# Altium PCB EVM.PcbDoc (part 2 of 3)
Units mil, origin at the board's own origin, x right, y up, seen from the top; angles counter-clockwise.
Board outline 4950 x 3450 mil, 6 copper layers (Top Layer, Power Layer 1 (PWR), Power Layer 2 (GND), Power Layer 3 (PWR), Power Layer 4 (GND), Bottom Layer), stack 58.4 mil thick; 378 components, 191 nets, 2749 pads, 0 vias.
Unrouted connection lines stored in the file: 482.
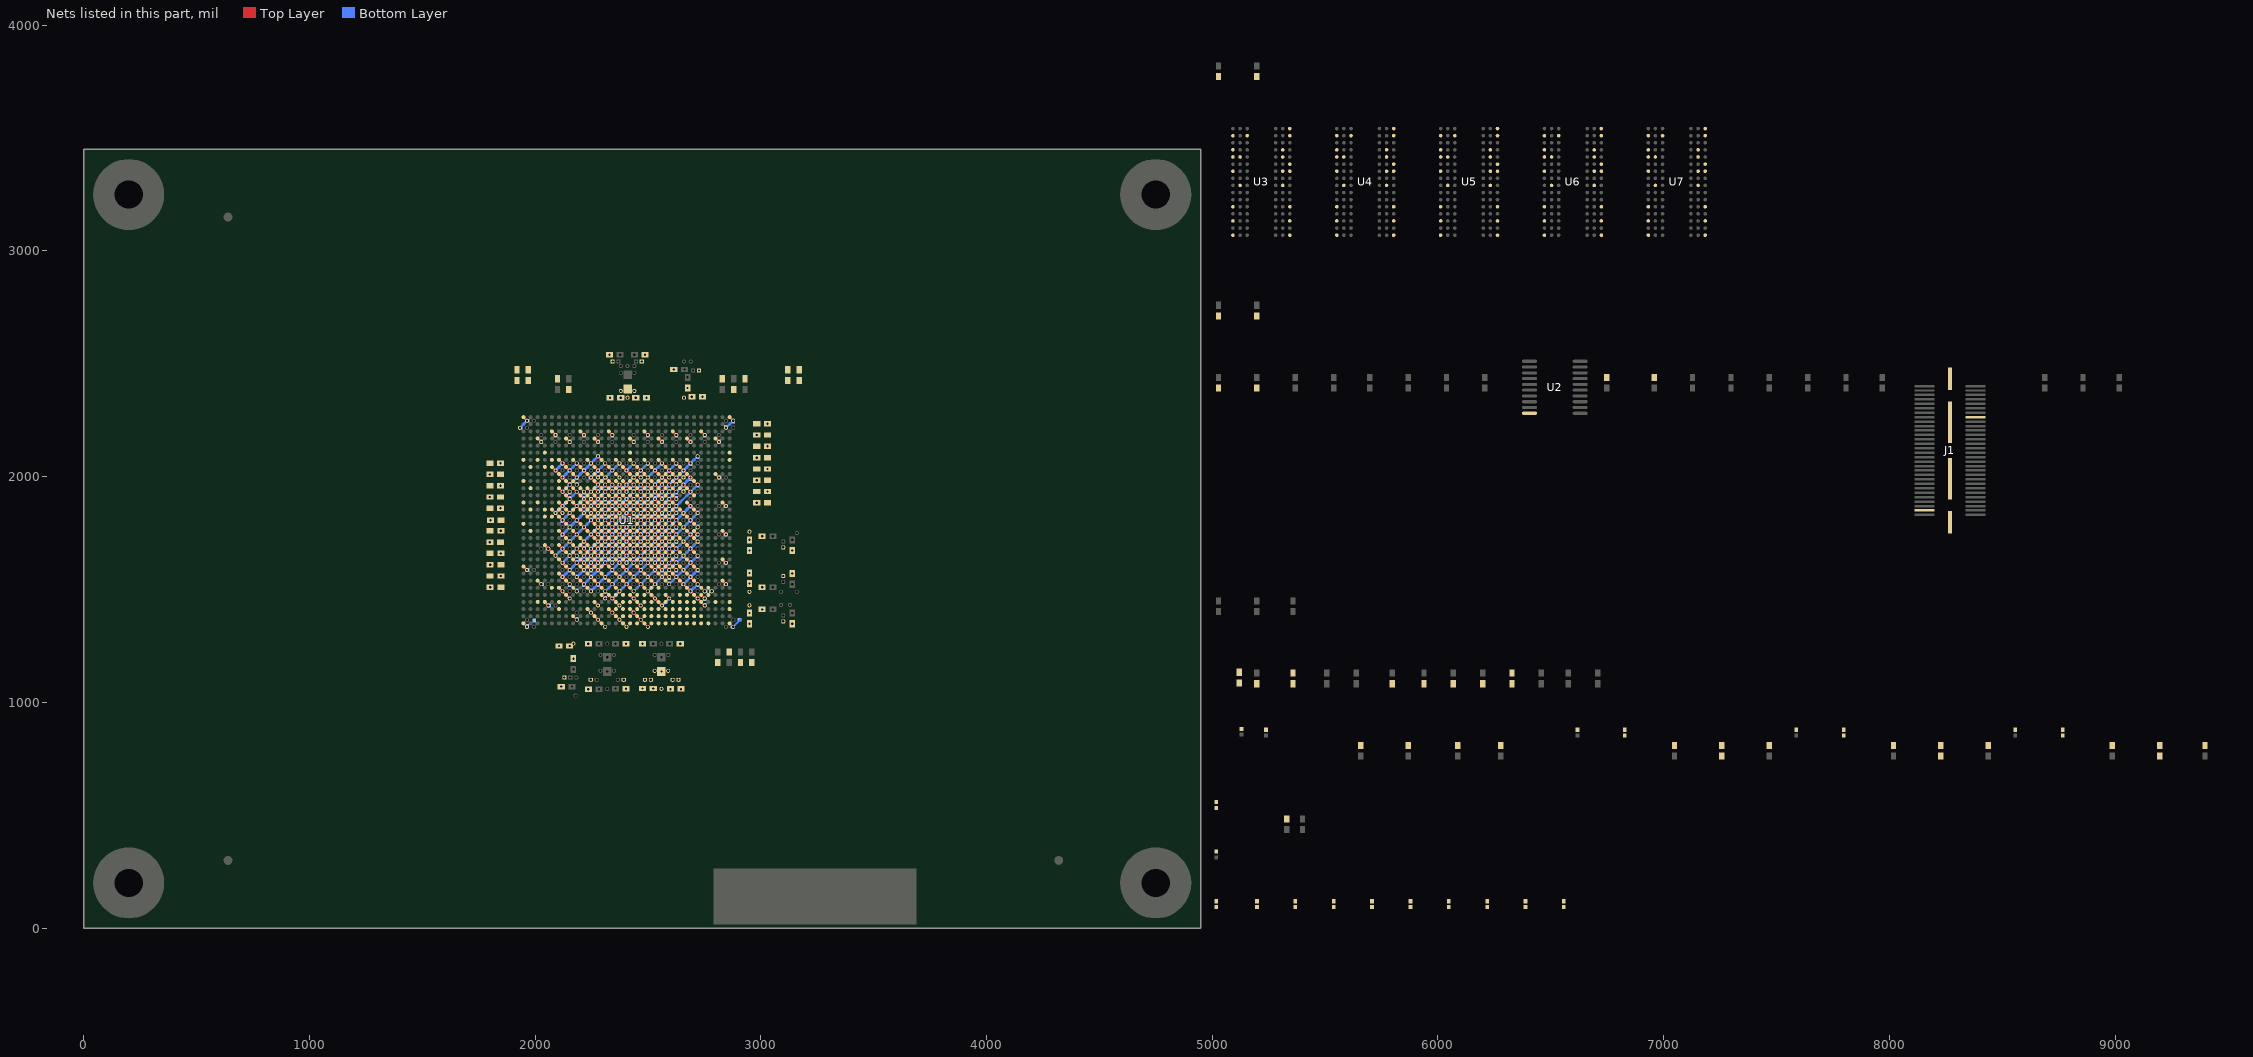
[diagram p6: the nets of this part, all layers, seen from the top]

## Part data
C1 C2 C3 C4 C5 C6 C7 C8 C9 C10 C11 C12 C13 C14 C15 C16 C17 C18 C19 C20 C21 C22 C23 C24 C25 C26 C27 C28 C29 C30 C31 C32 C33 C34 C35 C36 C37 C38 C39 C40 C41 C42 C43 C44 C45 C46 C47 C48 C49 C50 C51 C52 C53 C54 C55 C56 C57 C58 C59 C60 C61 C62 C63 C64 C65 C66 C67 C68 C69 C70 C71 C72 C73 C74 C75 C76 C77 C78 C79 C80 C109 C110 C111 C112 C113 C114 C115 C116 C117 C118 C119 C120 C121 C122 C123 C124 C136 C137 C138 C139 C140 C141 C142 C143 C144 C145 C146 C147 C148 C149 C150 C151 C152 C153 C154 C155 C156 C157 C158 C159 C160 C161 C162 C163 C164 C165 C166 C167 C168 C169 C170 C171 C172 C173 C174 C175 C176 C177 C178 C179 C180 C181 C182 C183 C184 C185 C186 C187 C188 C189 C190 C191 C192 C193 C194 C195 C196 C197 C198 C199 C200 C201 C202 C203 C204 C205 C206 C207 C208 C209 C210 C211 C212 C213 C214 C215 C216 C217 C218 C219 C220 C221 C222 C223 C224 C225 C226 C227 C235 C236 C237 C238 C239 C240 C241 C244 C246 C248 C249 C252 C253 C256 C257 C263 C264 C268 C269 C270 C271 C272 C273 C276 C279 C280 C283 C284 C285 C286 C287 C288 C289 C292 C295 C296 C299 C300 C303 C304 C307 C308: "CAP, CERM, 1000 pF, 25 V, +/- 10%, X7R, 0201"
C81 C82 C83 C84 C85 C86 C87 C88 C89 C90 C91 C92 C93 C94 C95 C96 C97 C98 C99 C100 C126 C127 C128 C129 C132 C133 C134 C135 C231 C232 C233 C234 C242 C243 C245 C247 C250 C251 C254 C255 C258 C259 C260 C261 C262 C265 C266 C267 C274 C275 C277 C278 C281 C282 C290 C291 C293 C294 C297 C298 C301 C302 C305 C306 C309 C310: "CAP, CERM, 0.1 µF, 6.3 V, +/- 10%, B, 0402"
C228: "CAP, TA, 100 µF, 6.3 V, +/- 20%, 0.018 ohm, SMD"
FID1 FID2 FID3: "Fiducial mark.  There is nothing to buy or mount."
H1 H2 H3 H4: "Machine Screw, Round, #4-40 x 1/4, Nylon, Philips panhead"
H5 H6 H7 H8: "Standoff, Hex, 0.5\"L #4-40 Nylon"
H9 H10 H11 H12: "Bumpon, Hemisphere, 0.44 X 0.20, Clear"
J1: "Receptacle, 0.5 mm, 30x2, Gold, TH"
L1 L6 L8: "Ferrite Bead, 120 ohm @ 100 MHz, 3 A, 0603"
L2 L3 L4 L5 L7 L9 L10 L11 L12: "Ferrite Bead, 120 ohm @ 100 MHz, 0.55 A, 0402"
LBL1: library part THT-14-423-10, "Thermal Transfer Printable Labels, 0.650\" W x 0.200\" H - 10,000 per roll"
Logo1: library part TI_Logo, "Texas Instrument Corporate Signature"
Logo2: library part Pb-Free
Logo3: library part FCC_disclaimer, "FCC_disclaimer"
R1 R2 R3 R17 R25 R33: "RES, 4.75 k, 1%, 0.063 W, 0402"
R4 R5 R6 R7 R8 R12: "RES, 1.00 k, 1%, 0.063 W, 0402"
R9 R11 R13 R18 R19: "RES, 100, 1%, 0.063 W, 0402"
R10 R14 R15 R16 R20 R21 R22 R23 R24 R26 R27 R28 R29 R30 R31 R32 R34: "RES, 10.0, 1%, 0.063 W, 0402"
R35 R36 R37 R38: "RES, 3.0 k, 5%, 0.063 W, 0402"
U1: library part lamarr_soc_TCI6630K2L, "Smallcell Baseband Processor with 4 C66x DSP Cores / 2 ARM A15 Cores / JESD / CPRI...etc"
U2: "OCTAL BUFFER/DRIVER WITH 3-STATE OUTPUTS, PW0020A"
U3 U4 U5 U6 U7: "4Gb DDR3-1600 SDRAM, 256Mb x 16, 1.25ns, 1.35V, 0 to 95 degC, 96-Ball FBGA, Pb-Free"
ZZ1: library part AssemblyNoteLabel
ZZ2 ZZ3 ZZ4: library part AssemblyNote

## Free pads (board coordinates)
  round 18 hole 10: 0(2122.05,2059.06) 0(2153.54,2027.56) 0(2185.04,1996.06) 0(2185.04,2059.05) 0(2216.54,2027.56) 0(2248.03,1933.07) 0(2248.03,1996.06) 0(2248.03,2059.06) 0(2279.53,1964.57) 0(2279.53,2027.56) 0(2279.53,2090.55) 0(2311.02,1964.57) 0(2311.02,1933.07) 0(2311.02,1996.06) 0(2311.02,2059.06) 0(2342.52,1870.08) 0(2342.52,1901.57) 0(2342.52,2027.56) 0(2374.02,1838.58) 0(2405.51,1964.57) 0(2437.01,1933.07) 0(2437.01,1964.57) 0(2468.5,1901.57) 0(2500,1870.08) 0(2500,1964.57) 0(2531.5,1838.58) 0(2562.99,1807.09) 0(2594.49,1775.59) 0(2625.98,1744.09) 0(2657.48,1712.6) 0(2688.98,1681.1) 0(2720.47,1649.61) 1(2279.53,1901.57) 1(2342.52,1933.07) 1(2342.52,1964.57) 1(2374.02,1870.08) 1(2405.51,1807.09) 1(2468.5,1933.07) 1(2531.5,1933.07) 2(2216.54,1933.07) 2(2279.53,1933.07) 2(2311.02,1870.08) 2(2374.02,1901.57) 2(2374.02,1933.07) 2(2374.02,1964.57) 2(2405.51,1838.58) 2(2405.51,1933.07) 2(2437.01,1775.59) 2(2500,1901.57) 2(2562.99,1901.57) 3(2342.52,1838.58) 3(2405.51,1901.57) 3(2437.01,1807.09) 3(2468.5,1744.09) 3(2562.99,1964.57) 4(2374.02,1807.09) 4(2437.01,1870.08) 4(2468.5,1775.59) 4(2500,1712.6) 4(2594.49,1933.07) 5(2405.51,1775.59) 5(2405.51,1618.11) 5(2468.5,1838.58) 5(2468.5,1618.11) 5(2500,1744.09) 5(2531.5,1681.1) 5(2594.49,1807.09) 5(2625.98,1901.57) 5(2625.98,1775.59) 5(2625.98,1838.58) 5(2625.98,1964.57) 6(2216.54,1870.08) 6(2437.01,1744.09) 6(2500,1807.09) 6(2531.5,1712.6) 6(2562.99,1649.61) 7(2248.03,1838.58) 7(2468.5,1712.6) 7(2531.5,1775.59) 7(2562.99,1681.1) 7(2594.49,1618.11) 8(2279.53,1807.09) 8(2311.02,1838.58) 8(2500,1681.1) 8(2562.99,1744.09) 8(2594.49,1649.61) 9(2311.02,1775.59) 9(2342.52,1807.09) 9(2531.5,1649.61) 9(2594.49,1712.6) 9(2625.98,1618.11) 10(2342.52,1744.09) 10(2374.02,1775.59) 10(2562.99,1618.11) 10(2625.98,1681.1) 10(2657.48,1586.61) 11(2374.02,1712.6) 11(2405.51,1744.09) 11(2594.49,1586.61) 11(2657.48,1649.61) 11(2688.98,1555.12) 12(2279.53,1744.09) 12(2437.01,1712.6) 12(2625.98,1555.12) 12(2688.98,1618.11) 12(2720.47,1523.62) 12(2783.46,1492.13) 13(2311.02,1712.6) 13(2468.63,1681.23) 13(2657.48,1523.62) 13(2720.47,1586.61) 14(2342.52,1681.1) 14(2500,1649.61) 14(2531.5,1618.11) 14(2562.99,1586.61) 14(2625.98,1586.61) 14(2688.98,1492.13) 15(2153.54,1933.07) 15(2185.04,1649.61) 15(2248.03,1901.57) 15(2279.53,1870.08) 15(2279.53,1681.1) 15(2311.02,1901.57) 15(2374.02,1649.61) 15(2405.51,1681.1) 15(2405.51,1870.08) 15(2437.01,1649.61) 15(2437.01,1901.57) 15(2531.5,1870.08) 15(2562.99,1838.58) 15(2594.49,1555.12) 15(2594.49,1870.08) 15(2657.48,1933.07) 15(2720.47,1460.63) 16(2311.02,1649.61) 16(2751.97,1429.13) 17(1800,1710) 17(1800,1910) 17(1800,2010) 17(1801.38,1510) 17(1801.38,1610) 17(1802.76,1806.65) 17(1847.24,1860) 17(1847.24,1960) 17(1847.24,2060) 17(1848.62,1560) 17(1848.62,1660) 17(1848.62,1760) 17(2090.55,2027.56) 17(2342.52,1618.11) 17(2982.28,1884.25) 17(2982.28,1984.25) 17(2982.28,2084.25) 17(2982.28,2184.25) 17(3029.53,1934.25) 17(3029.53,2034.25) 17(3029.53,2134.25) 17(3029.53,2234.25) 18(2122.05,1996.06) 18(2216.54,1681.1) 19(2153.54,1964.57) 19(2248.03,1649.61) 20(2185.04,1933.07) 20(2279.53,1618.11) 21(2216.54,1901.57) 21(2216.54,1618.11) 22(2248.03,1870.08) 22(2248.03,1586.61) 23(2279.53,1838.58) 24(2311.02,1807.09) 24(2437.01,1838.58) 24(2468.5,1870.08) 25(2342.52,1775.59) 25(2500,1838.58) 26(2374.02,1744.09) 26(2531.5,1807.09) 27(2405.51,1712.6) 27(2562.99,1775.59) 28(2437.01,1681.1) 28(2594.49,1744.09) 29(2468.5,1649.61) 29(2625.98,1712.6) 30(2468.5,1807.09) 30(2500,1618.11) 31(2500,1775.59) 31(2531.5,1586.61) 32(2531.5,1744.09) 32(2562.99,1555.12) 33(2562.99,1712.6) 33(2594.49,1523.62) 34(2122.05,1933.07) 34(2594.49,1681.1) 35(2153.54,1901.57) 35(2625.98,1649.61) 36(2185.04,1870.08) 37(2216.54,1838.58) 38(2248.03,1807.09) 39(2279.53,1775.59) 40(2311.02,1744.09) 41(2342.52,1712.6) 42(2374.02,1681.1) 43(2405.51,1649.61) 44(2437.01,1618.11) 45(2468.5,1586.61) 46(2500,1555.12) 47(2531.5,1523.62) 49(2594.49,1460.63) 51(2090.55,1838.58) 51(2122.05,1744.09) 51(2122.05,1838.58) 51(2122.05,1870.08) 52(2122.05,1807.09) 52(2153.54,1712.6) 52(2153.54,1838.58) 53(2153.54,1775.59) 53(2185.04,1681.1) 53(2185.04,1807.09) 54(2185.04,1744.09) 54(2216.54,1649.61) 54(2216.54,1775.59) 55(2216.54,1712.6) 55(2248.03,1618.11) 55(2248.03,1744.09) 56(2248.03,1681.1) 56(2279.53,1586.61) 56(2279.53,1712.6) 57(2279.53,1649.61) 57(2311.02,1555.12) 57(2311.02,1681.1) 57(2311.02,1523.62) 57(2342.52,1555.12) 57(2374.02,1523.62) 57(2374.02,1586.61) 57(2405.51,1555.12) 57(2437.01,1523.62) 57(2437.01,1586.61) 57(2468.5,1555.12) 57(2500,1523.62) 57(2500,1586.61) 57(2531.5,1555.12) 57(2562.99,1523.62) 57(2625.98,1523.62) 58(2311.02,1618.11) 58(2342.52,1523.62) 58(2342.52,1649.61) 59(2342.52,1586.61) 59(2374.02,1492.13) 59(2374.02,1618.11) 60(2122.05,1681.1) 60(2374.02,1555.12) 60(2405.51,1586.61) 61(2153.54,1649.61) 61(2405.51,1523.62) 61(2437.01,1555.12) 62(2153.54,1618.11) 62(2185.04,1618.11) 62(2437.01,1492.13) 62(2468.5,1523.62) 63(2216.54,1586.61) 63(2500,1492.13) 64(2248.03,1555.12) 64(2531.5,1460.63) 65(2279.53,1523.62) 65(2562.99,1429.13) 66(2311.02,1492.13) 67(1964.57,1334.65) 67(1964.57,1366.14) 67(1964.57,1586.61) 67(1996.06,1334.65) 67(1996.06,1586.61) 67(2027.56,1523.62) 67(2027.56,1681.1) 67(2059.06,1429.13) 67(2059.06,1523.62) 67(2090.55,1429.13) 67(2106.38,1250) 67(2116.38,1070) 67(2122.05,1523.62) 67(2122.05,1555.12) 67(2122.05,1586.61) 67(2122.05,1649.61) 67(2122.05,1712.6) 67(2122.05,1492.13) 67(2122.05,1775.59) 67(2130,1110) 67(2153.54,1460.63) 67(2153.54,1492.13) 67(2153.54,1523.62) 67(2153.54,1555.12) 67(2153.54,1681.1) 67(2153.54,1744.09) 67(2153.54,1807.09) 67(2153.62,1250) 67(2155.98,1110) 67(2163.62,1070) 67(2170,1146.38) 67(2170,1193.62) 67(2170,1260) 67(2180,1030) 67(2182.99,1110) 67(2185.04,1492.13) 67(2185.04,1775.59) 67(2185.04,1366.14) 67(2185.04,1397.64) 67(2185.04,1523.62) 67(2185.04,1586.61) 67(2216.54,1492.13) 67(2216.54,1555.12) 67(2236.38,1058.5) 67(2236.38,1260) 67(2247.01,1100) 67(2248.03,1397.64) 67(2248.03,1523.62) 67(2272.99,1100) 67(2279.53,1492.13) 67(2279.53,1366.14) 67(2279.53,1429.13) 67(2279.53,1555.12) 67(2283.62,1058.5) 67(2283.62,1260) 67(2290,1140) 67(2290,1210) 67(2311.02,1334.65) 67(2311.02,1460.63) 67(2320,1060) 67(2320,1137.01) 67(2320,1200) 67(2320,1260) 67(2342.52,1460.63) 67(2342.52,1397.64) 67(2350,1140) 67(2350,1210) 67(2356.38,1061.5) 67(2356.38,1260) 67(2367.01,1100) 67(2374.02,1366.14) 67(2392.99,1100) 67(2403.62,1060) 67(2403.62,1260) 67(2405.51,1334.65) 67(2437.01,1397.64) 67(2468.5,1366.14) 67(2476.38,1061.5) 67(2476.38,1260) 67(2487.01,1100) 67(2500,1334.65) 67(2512.99,1100) 67(2523.62,1061.5) 67(2523.62,1260) 67(2530,1140) 67(2530,1210) 67(2560,1060) 67(2560,1137.01) 67(2560,1200) 67(2560,1260) 67(2590,1140) 67(2590.55,1210.16) 67(2596.38,1260) 67(2600,1058.5) 67(2610,1100) 67(2635.98,1100) 67(2643.62,1260) 67(2647.24,1058.5) 68(2374.02,1429.13) 68(2437.01,1460.63) 68(2468.5,1429.13) 69(2059.06,1681.1) 70(2090.55,1649.61) 71(2122.05,1618.11) 72(2153.54,1586.61) 73(2185.04,1555.12) 74(2216.54,1523.62) 75(2248.03,1492.13) 78(2374.02,2059.06) 79(2122.05,2027.56) 79(2153.54,1996.06) 79(2153.54,2059.06) 79(2185.04,2027.56) 79(2216.54,1996.06) 79(2216.54,2059.06) 79(2248.03,2027.56) 79(2279.53,2059.06) 79(2311.02,2027.56) 79(2342.52,1996.06) 79(2342.52,2059.06) 79(2374.02,2027.56) 79(2405.51,1996.06) 79(2405.51,2027.56) 79(2405.51,2059.06) 79(2437.01,2027.56) 79(2468.5,2059.06) 79(2500,2027.56) 79(2531.5,2059.06) 79(2562.99,2027.56) 79(2594.49,2059.06) 79(2625.98,2027.56) 79(2657.48,2059.06) 79(2688.98,2027.56) 79(2720.47,2059.06) 80(2437.01,1996.06) 81(2468.5,1964.57) 82(2500,1933.07) 83(2531.5,1901.58) 84(2562.99,1870.08) 85(2594.49,1838.58) 86(2625.98,1807.09) 86(2657.48,1775.59) 86(2688.98,1744.09) 87(2437.01,2059.06) 88(2468.5,2027.56) 89(2500,1996.06) 90(2531.5,1964.57) 91(2562.99,1933.07) 92(2594.49,1901.58) 93(2625.98,1870.08) 94(2657.48,1838.58) 95(2688.98,1807.09) 95(2720.47,1744.09) 95(2720.47,1775.59) 96(2500,2059.06) 97(2531.5,2027.56) 98(2185.04,1964.57) 98(2279.53,1996.06) 98(2330,2540) 98(2332.76,2350) 98(2344.02,2510) 98(2370,2510) 98(2374.02,1996.06) 98(2377.24,2540) 98(2380,2350) 98(2380,2380) 98(2380,2460) 98(2380,2490) 98(2410,2350) 98(2410,2490) 98(2440,2380) 98(2440,2460) 98(2440,2490) 98(2440,2540) 98(2446.38,2350) 98(2447.01,2510) 98(2468.5,1996.06) 98(2472.99,2510) 98(2487.24,2540) 98(2493.62,2350) 98(2531.5,1996.06) 98(2562.99,1996.06) 98(2594.49,1996.06) 99(2594.49,1964.57) 100(1933.07,2216.54) 100(1964.57,2216.54) 100(1964.57,2248.03) 100(1996.06,2248.03) 100(2027.56,2185.04) 100(2027.56,2153.54) 100(2090.55,2153.54) 100(2090.55,2185.04) 100(2153.54,2153.54) 100(2153.54,2185.04) 100(2216.54,2153.54) 100(2216.54,2185.04) 100(2279.53,2153.54) 100(2279.53,2185.04) 100(2342.52,2153.54) 100(2342.52,2185.04) 100(2437.01,2153.54) 100(2437.01,2185.04) 100(2500,2153.54) 100(2500,2185.04) 100(2562.99,2059.06) 100(2562.99,2153.54) 100(2562.99,2185.04) 100(2594.49,2027.56) 100(2614.65,2474.49) 100(2625.98,1933.07) 100(2625.98,1996.06) 100(2625.98,2059.06) 100(2625.98,2153.54) 100(2625.98,2185.04) 100(2657.48,1555.12) 100(2657.48,1618.11) 100(2657.48,1681.1) 100(2657.48,1744.09) 100(2657.48,1807.09) 100(2657.48,1964.57) 100(2657.48,1996.06) 100(2657.48,2027.56) 100(2660,2350) 100(2660,2510) 100(2661.89,2474.49) 100(2676.06,2392.76) 100(2676.06,2440) 100(2688.98,1523.62) 100(2688.98,1586.61) 100(2688.98,1649.61) 100(2688.98,1712.6) 100(2688.98,1775.59) 100(2688.98,1838.58) 100(2688.98,1901.57) 100(2688.98,1933.07) 100(2688.98,1964.57) 100(2688.98,1996.06) 100(2688.98,2059.06) 100(2688.98,2153.54) 100(2688.98,2185.04) 100(2690,2510) 100(2694.65,2354.49) 100(2700,2470) 100(2720.47,1933.07) 100(2720.47,1492.13) 100(2720.47,1555.12) 100(2720.47,1618.11) 100(2720.47,1681.1) 100(2720.47,1807.09) 100(2720.47,1870.08) 100(2720.47,1964.57) 100(2720.47,2090.55) 100(2725.98,2470) 100(2741.89,2354.49) 100(2751.97,1460.63) 100(2751.97,1492.13) 100(2751.97,2153.54) 100(2751.97,2185.04) 100(2814.96,1523.62) 100(2814.96,1618.11) 100(2814.96,1744.09) 100(2814.96,1870.08) 100(2814.96,1996.06) 100(2814.96,2153.54) 100(2814.96,2185.04) 100(2846.46,1334.65) 100(2846.46,1618.11) 100(2846.46,1523.62) 100(2846.46,1744.09) 100(2846.46,1870.08) 100(2846.46,1996.06) 100(2846.46,2216.54) 100(2846.46,2248.03) 100(2877.95,1334.65) 100(2877.95,1366.14) 100(2877.95,2216.54) 100(2877.95,2248.03) 100(2950,1348.38) 100(2950,1395.62) 100(2950,1430) 100(2950,1490) 100(2950,1526.38) 100(2950,1573.62) 100(2950,1672.76) 100(2950,1720) 100(2950,1756.38) 100(3006.38,1412) 100(3006.38,1510) 100(3006.38,1736.38) 100(3053.62,1412) 100(3053.62,1510) 100(3053.62,1736.38) 100(3090,1432) 100(3090,1490) 100(3100,1359.01) 100(3100,1384.99) 100(3100,1534.02) 100(3100,1560) 100(3100,1687.01) 100(3100,1712.99) 100(3130,1432) 100(3140,1348.38) 100(3140,1395.62) 100(3140,1523.39) 100(3140,1570.63) 100(3140,1672.76) 100(3140,1720) 100(3160,1490) 100(3160,1750) 102(2688.98,1870.08) 103(2720.47,1838.58)
  round 18 hole 10 paste+0: 86(2720.47,1712.6)

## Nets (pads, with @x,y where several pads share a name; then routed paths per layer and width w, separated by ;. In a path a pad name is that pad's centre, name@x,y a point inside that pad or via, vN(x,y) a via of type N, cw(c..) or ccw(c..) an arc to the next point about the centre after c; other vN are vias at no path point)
GND: C1.2 C2.2 C3.2 C4.2 C5.2 C6.2 C7.2 C8.2 C9.2 C10.2 C11.2 C12.2 C13.2 C14.2 C15.2 C16.2 C17.2 C18.2 C19.2 C20.2 C21.2 C22.2 C23.2 C24.2 C25.2 C26.2 C27.2 C28.2 C29.2 C30.2 C31.2 C32.2 C33.2 C34.2 C35.2 C36.2 C37.2 C38.2 C39.2 C40.2 C41.2 C42.2 C43.2 C44.2 C45.2 C46.2 C47.2 C48.2 C49.2 C50.2 C51.2 C52.2 C53.2 C54.2 C55.2 C56.2 C57.2 C58.2 C59.2 C60.2 C61.2 C62.2 C63.2 C64.2 C65.2 C66.2 C67.2 C68.2 C69.2 C70.2 C71.2 C72.2 C73.2 C74.2 C75.2 C76.2 C77.2 C78.2 C79.2 C80.2 C81.2 C82.2 C83.2 C84.2 C85.2 C86.2 C87.2 C88.2 C89.2 C90.2 C91.2 C92.2 C93.2 C94.2 C95.2 C96.2 C97.2 C98.2 C99.2 C100.2 C109.2 C110.2 C111.2 C112.2 C113.2 C114.2 C115.2 C116.2 C117.2 C118.2 C119.2 C120.2 C121.2 C122.2 C123.2 C124.2 C126.2 C127.2 C128.2 C129.2 C132.2 C133.2 C134.2 C135.2 C136.2 C137.2 C138.2 C139.2 C140.2 C141.2 C142.2 C143.2 C144.2 C145.2 C146.2 C147.2 C148.2 C149.2 C150.2 C151.2 C152.2 C153.2 C154.2 C155.2 C156.2 C157.2 C158.2 C159.2 C160.2 C161.2 C162.2 C163.2 C164.2 C165.2 C166.2 C167.2 C168.2 C169.2 C170.2 C171.2 C172.2 C173.2 C174.2 C175.2 C176.2 C177.2 C178.2 C179.2 C180.2 C181.2 C182.2 C183.2 C184.2 C185.2 C186.2 C187.2 C188.2 C189.2 C190.2 C191.2 C192.2 C193.2 C194.2 C195.2 C196.2 C197.2 C198.2 C199.2 C200.2 C201.2 C202.2 C203.2 C204.2 C205.2 C206.2 C207.2 C208.2 C209.2 C210.2 C211.2 C212.2 C213.2 C214.2 C215.2 C216.2 C217.2 C218.2 C219.2 C220.2 C221.2 C222.2 C223.2 C224.2 C225.2 C226.2 C227.2 C228.2 C231.2 C232.2 C233.2 C234.2 C235.2 C236.2 C237.2 C238.2 C239.2 C240.2 C241.2 C242.2 C243.2 C244.2 C245.2 C246.2 C247.2 C248.2 C249.2 C250.2 C251.2 C252.2 C253.2 C254.2 C255.2 C256.2 C257.2 C258.2 C259.2 C260.2 C261.2 C262.2 C263.2 C264.2 C265.2 C266.2 C267.2 C268.2 C269.2 C270.2 C271.2 C272.2 C273.2 C274.2 C275.2 C276.2 C277.2 C278.2 C279.2 C280.2 C281.2 C282.2 C283.2 C284.2 C285.2 C286.2 C287.2 C288.2 C289.2 C290.2 C291.2 C292.2 C293.2 C294.2 C295.2 C296.2 C297.2 C298.2 C299.2 C300.2 C301.2 C302.2 C303.2 C304.2 C305.2 C306.2 C307.2 C308.2 C309.2 C310.2 J1.16 J1.57 J1.MP1 J1.MP2 J1.MP3 J1.MP4 pad.0@2122.05,2059.06 pad.0@2153.54,2027.56 pad.0@2185.04,1996.06 pad.0@2185.04,2059.05 pad.0@2216.54,2027.56 pad.0@2248.03,1933.07 pad.0@2248.03,1996.06 pad.0@2248.03,2059.06 pad.0@2279.53,1964.57 pad.0@2279.53,2027.56 pad.0@2279.53,2090.55 pad.0@2311.02,1933.07 pad.0@2311.02,1996.06 pad.0@2311.02,2059.06 pad.0@2342.52,1901.57 pad.0@2342.52,2027.56 pad.0@2405.51,1964.57 pad.0@2437.01,1933.07 pad.0@2468.5,1901.57 pad.0@2500,1870.08 pad.0@2531.5,1838.58 pad.0@2562.99,1807.09 pad.0@2594.49,1775.59 pad.0@2625.98,1744.09 pad.0@2657.48,1712.6 pad.0@2688.98,1681.1 pad.0@2720.47,1649.61 pad.1@2279.53,1901.57 pad.1@2342.52,1964.57 pad.1@2374.02,1870.08 pad.2@2311.02,1870.08 pad.2@2374.02,1933.07 pad.2@2405.51,1838.58 pad.3@2342.52,1838.58 pad.3@2405.51,1901.57 pad.3@2437.01,1807.09 pad.4@2374.02,1807.09 pad.4@2437.01,1870.08 pad.4@2468.5,1775.59 pad.5@2405.51,1775.59 pad.5@2468.5,1838.58 pad.5@2500,1744.09 pad.6@2437.01,1744.09 pad.6@2500,1807.09 pad.6@2531.5,1712.6 pad.7@2468.5,1712.6 pad.7@2531.5,1775.59 pad.7@2562.99,1681.1 pad.8@2500,1681.1 pad.8@2562.99,1744.09 pad.8@2594.49,1649.61 pad.9@2531.5,1649.61 pad.9@2594.49,1712.6 pad.9@2625.98,1618.11 pad.10@2562.99,1618.11 pad.10@2625.98,1681.1 pad.10@2657.48,1586.61 pad.11@2594.49,1586.61 pad.11@2657.48,1649.61 pad.11@2688.98,1555.12 pad.12@2625.98,1555.12 pad.12@2688.98,1618.11 pad.12@2720.47,1523.62 pad.12@2783.46,1492.13 pad.13@2657.48,1523.62 pad.13@2720.47,1586.61 pad.14@2688.98,1492.13 pad.15@2720.47,1460.63 pad.16@2751.97,1429.13 pad.17@1800,1710 pad.17@1800,1910 pad.17@1800,2010 pad.17@1801.38,1510 pad.17@1801.38,1610 pad.17@1802.76,1806.65 pad.17@1847.24,1860 pad.17@1847.24,1960 pad.17@1847.24,2060 pad.17@1848.62,1560 pad.17@1848.62,1660 pad.17@1848.62,1760 pad.17@2090.55,2027.56 pad.17@2982.28,1884.25 pad.17@2982.28,1984.25 pad.17@2982.28,2084.25 pad.17@2982.28,2184.25 pad.17@3029.53,1934.25 pad.17@3029.53,2034.25 pad.17@3029.53,2134.25 pad.17@3029.53,2234.25 pad.18@2122.05,1996.06 pad.19@2153.54,1964.57 pad.20@2185.04,1933.07 pad.21@2216.54,1901.57 pad.22@2248.03,1870.08 pad.23 pad.24@2311.02,1807.09 pad.25@2342.52,1775.59 pad.26@2374.02,1744.09 pad.27@2405.51,1712.6 pad.28@2437.01,1681.1 pad.29@2468.5,1649.61 pad.30@2500,1618.11 pad.31@2531.5,1586.61 pad.32@2562.99,1555.12 pad.33@2594.49,1523.62 pad.34@2122.05,1933.07 pad.35@2153.54,1901.57 pad.36 pad.37 pad.38 pad.39 pad.40 pad.41 pad.42 pad.43 pad.44 pad.45 pad.46 pad.47 pad.49 pad.51 pad.52 pad.53 pad.54 pad.55 pad.56 pad.57@2279.53,1649.61 pad.57@2311.02,1555.12 pad.57@2311.02,1681.1 pad.58 pad.59 pad.60 pad.61 pad.62@2185.04,1618.11 pad.62@2437.01,1492.13 pad.62@2468.5,1523.62 pad.63 pad.64 pad.65 pad.66 pad.67@1964.57,1334.65 pad.67@1964.57,1586.61 pad.67@2027.56,1523.62 pad.67@2059.06,1429.13 pad.67@2106.38,1250 pad.67@2116.38,1070 pad.67@2122.05,1492.13 pad.67@2122.05,1555.12 pad.67@2130,1110 pad.67@2153.54,1460.63 pad.67@2153.54,1523.62 pad.67@2185.04,1366.14 pad.67@2185.04,1492.13 pad.67@2236.38,1058.5 pad.67@2236.38,1260 pad.67@2247.01,1100 pad.67@2248.03,1397.64 pad.67@2279.53,1366.14 pad.67@2279.53,1429.13 pad.67@2311.02,1334.65 pad.67@2342.52,1397.64 pad.67@2342.52,1460.63 pad.67@2374.02,1366.14 pad.67@2392.99,1100 pad.67@2403.62,1060 pad.67@2403.62,1260 pad.67@2405.51,1334.65 pad.67@2437.01,1397.64 pad.67@2468.5,1366.14 pad.67@2476.38,1061.5 pad.67@2476.38,1260 pad.67@2487.01,1100 pad.67@2500,1334.65 pad.67@2635.98,1100 pad.67@2643.62,1260 pad.67@2647.24,1058.5 pad.68 pad.69 pad.70 pad.71 pad.72 pad.73 pad.74 pad.75 pad.78 pad.79@2405.51,2027.56 pad.80 pad.81 pad.82 pad.83 pad.84 pad.85 pad.86 pad.87 pad.88 pad.89 pad.90 pad.91 pad.92 pad.93 pad.94 pad.95@2688.98,1807.09 pad.95@2720.47,1775.59 pad.96 pad.97 pad.98@2330,2540 pad.98@2332.76,2350 pad.98@2344.02,2510 pad.98@2472.99,2510 pad.98@2487.24,2540 pad.98@2493.62,2350 pad.98@2562.99,1996.06 pad.99 pad.100@1933.07,2216.54 pad.100@1964.57,2248.03 pad.100@2027.56,2153.54 pad.100@2090.55,2185.04 pad.100@2153.54,2153.54 pad.100@2216.54,2185.04 pad.100@2279.53,2153.54 pad.100@2342.52,2185.04 pad.100@2437.01,2153.54 pad.100@2500,2185.04 pad.100@2562.99,2059.06 pad.100@2562.99,2153.54 pad.100@2594.49,2027.56 pad.100@2614.65,2474.49 pad.100@2625.98,1933.07 pad.100@2625.98,1996.06 pad.100@2625.98,2059.06 pad.100@2625.98,2185.04 pad.100@2657.48,1964.57 pad.100@2657.48,2027.56 pad.100@2688.98,1933.07 pad.100@2688.98,1996.06 pad.100@2688.98,2059.06 pad.100@2688.98,2153.54 pad.100@2720.47,1964.57 pad.100@2720.47,2090.55 pad.100@2725.98,2470 pad.100@2741.89,2354.49 pad.100@2751.97,2185.04 pad.100@2814.96,1996.06 pad.100@2814.96,2153.54 pad.100@2846.46,1523.62 pad.100@2846.46,1618.11 pad.100@2846.46,1744.09 pad.100@2846.46,1870.08 pad.100@2846.46,2216.54 pad.100@2877.95,1334.65 pad.100@2877.95,2248.03 pad.100@2950,1348.38 pad.100@2950,1573.62 pad.100@2950,1672.76 pad.100@3100,1359.01 pad.100@3100,1560 pad.100@3100,1687.01 pad.100@3140,1348.38 pad.100@3140,1570.63 pad.100@3140,1672.76 pad.102 pad.103 R4.1 R5.1 R6.1 R7.1 R8.1 R12.1 R26.2 R33.1 R34.1 R35.1 R36.1 R37.1 R38.1 U1.A1 U1.A30 U1.AA6 U1.AA8 U1.AA10 U1.AA12 U1.AA14 U1.AA16 U1.AA18 U1.AA20 U1.AA22 U1.AA24 U1.AA29 U1.AB1 U1.AB7 U1.AB9 U1.AB11 U1.AB13 U1.AB15 U1.AB17 U1.AB19 U1.AB21 U1.AB23 U1.AB25 U1.AC6 U1.AC8 U1.AC10 U1.AC12 U1.AC14 U1.AC16 U1.AC18 U1.AC20 U1.AC22 U1.AC24 U1.AD3 U1.AD7 U1.AD9 U1.AD11 U1.AD13 U1.AD15 U1.AD17 U1.AD19 U1.AD21 U1.AD23 U1.AD25 U1.AD29 U1.AE6 U1.AE8 U1.AE10 U1.AE12 U1.AE14 U1.AE16 U1.AE18 U1.AE24 U1.AF7 U1.AF13 U1.AF16 U1.AF19 U1.AF21 U1.AF25 U1.AG4 U1.AG11 U1.AG14 U1.AG17 U1.AG20 U1.AG23 U1.AG26 U1.AG28 U1.AH10 U1.AH13 U1.AH16 U1.AH19 U1.AH22 U1.AH25 U1.AJ8 U1.AJ11 U1.AJ14 U1.AJ17 U1.AJ20 U1.AJ23 U1.AJ26 U1.AK1 U1.AK12 U1.AK15 U1.AK18 U1.AK21 U1.AK24 U1.AK27 U1.AK30 U1.C5 U1.C9 U1.C13 U1.C18 U1.C22 U1.C26 U1.D3 U1.D7 U1.D11 U1.D16 U1.D20 U1.D24 U1.D28 U1.F4 U1.F16 U1.G1 U1.G3 U1.G5 U1.G6 U1.G8 U1.G10 U1.G12 U1.G14 U1.G16 U1.G18 U1.G20 U1.G22 U1.G24 U1.H2 U1.H4 U1.H5 U1.H7 U1.H9 U1.H11 U1.H13 U1.H15 U1.H17 U1.H19 U1.H21 U1.H23 U1.J6 U1.J8 U1.J10 U1.J12 U1.J16 U1.J18 U1.J20 U1.J22 U1.J24 U1.J28 U1.K1 U1.K6 U1.K7 U1.K11 U1.K13 U1.K15 U1.K17 U1.K19 U1.K21 U1.K23 U1.K25 U1.L2 U1.L6 U1.L8 U1.L10 U1.L12 U1.L14 U1.L16 U1.L18 U1.L20 U1.L22 U1.L24 U1.M7 U1.M9 U1.M11 U1.M13 U1.M15 U1.M17 U1.M19 U1.M21 U1.M25 U1.N1 U1.N3 U1.N6 U1.N7 U1.N8 U1.N10 U1.N12 U1.N14 U1.N16 U1.N18 U1.N20 U1.N22 U1.N24 U1.N29 U1.P2 U1.P4 U1.P5 U1.P6 U1.P7 U1.P8 U1.P9 U1.P11 U1.P13 U1.P15 U1.P17 U1.P19 U1.P21 U1.P23 U1.P25 U1.R4 U1.R5 U1.R6 U1.R8 U1.R10 U1.R12 U1.R14 U1.R16 U1.R18 U1.R20 U1.R22 U1.R24 U1.T1 U1.T7 U1.T9 U1.T11 U1.T13 U1.T15 U1.T17 U1.T19 U1.T21 U1.T23 U1.T25 U1.U2 U1.U6 U1.U8 U1.U10 U1.U12 U1.U14 U1.U16 U1.U18 U1.U20 U1.U22 U1.U24 U1.U29 U1.V7 U1.V9 U1.V11 U1.V13 U1.V15 U1.V17 U1.V19 U1.V21 U1.V23 U1.V25 U1.W4 U1.W6 U1.W8 U1.W10 U1.W12 U1.W14 U1.W16 U1.W18 U1.W20 U1.W22 U1.W24 U1.Y5 U1.Y7 U1.Y9 U1.Y11 U1.Y13 U1.Y15 U1.Y17 U1.Y19 U1.Y21 U1.Y23 U1.Y25 U2.10 U3.A9 U3.B1 U3.B3 U3.B9 U3.D1 U3.D8 U3.E1 U3.E2 U3.E8 U3.F9 U3.G1 U3.G8 U3.G9 U3.J2 U3.J8 U3.M1 U3.M9 U3.P1 U3.P9 U3.T1 U3.T9 U4.A9 U4.B1 U4.B3 U4.B9 U4.D1 U4.D8 U4.E1 U4.E2 U4.E8 U4.F9 U4.G1 U4.G8 U4.G9 U4.J2 U4.J8 U4.M1 U4.M9 U4.P1 U4.P9 U4.T1 U4.T9 U5.A9 U5.B1 U5.B3 U5.B9 U5.D1 U5.D8 U5.E1 U5.E2 U5.E8 U5.F9 U5.G1 U5.G8 U5.G9 U5.J2 U5.J8 U5.M1 U5.M9 U5.P1 U5.P9 U5.T1 U5.T9 U6.A9 U6.B1 U6.B3 U6.B9 U6.D1 U6.D8 U6.E1 U6.E2 U6.E8 U6.F9 U6.G1 U6.G8 U6.G9 U6.J2 U6.J8 U6.M1 U6.M9 U6.P1 U6.P9 U6.T1 U6.T9 U7.A9 U7.B1 U7.B3 U7.B9 U7.D1 U7.D8 U7.E1 U7.E2 U7.E8 U7.F9 U7.G1 U7.G8 U7.G9 U7.J2 U7.J8 U7.M1 U7.M9 U7.P1 U7.P9 U7.T1 U7.T9 | length 16792.4
  Top Layer w10: U1.AK1@1948.82,1350.39 pad.67@1964.57,1334.65 ; U1.AB1@1948.82,1602.36 pad.67@1964.57,1586.61 ; U1.A1@1948.82,2263.78 pad.100@1964.57,2248.03 ; U1.AD3@2011.81,1539.37 pad.67@2027.56,1523.62 ; U1.D3@2011.81,2169.29 pad.100@2027.56,2153.54 ; U1.AG4@2043.31,1444.88 pad.67@2059.06,1429.13 ; U1.W4@2043.31,1696.85 U1.AA6@2106.3,1633.86 U1.AB7@2137.8,1602.36 pad.72@2153.54,1586.61 U1.AD9@2200.79,1539.37 U1.AE10@2232.28,1507.87 pad.75@2248.03,1492.13 ; U1.P5@2074.8,1854.33 pad.51@2090.55,1838.58 U1.R6@2106.3,1822.83 pad.52@2122.05,1807.09 pad.53@2153.54,1775.59 pad.54@2185.04,1744.09 U1.V9@2200.79,1728.35 pad.55@2216.54,1712.6 U1.W10@2232.28,1696.85 pad.56@2248.03,1681.1 U1.Y11@2263.78,1665.35 pad.57@2279.53,1649.61 U1.AA12@2295.28,1633.86 pad.58@2311.02,1618.11 U1.AB13@2326.77,1602.36 pad.59@2342.52,1586.61 U1.AC14@2358.27,1570.87 pad.60@2374.02,1555.12 pad.61@2405.51,1523.62 U1.AE16@2421.26,1507.87 pad.62@2437.01,1492.13 ; U1.H5@2074.8,2043.31 pad.17@2090.55,2027.56 U1.J6@2106.3,2011.81 pad.18@2122.05,1996.06 U1.K7@2137.8,1980.31 pad.19@2153.54,1964.57 pad.20@2185.04,1933.07 U1.M9@2200.79,1917.32 pad.21@2216.54,1901.57 U1.N10@2232.28,1885.83 pad.22@2248.03,1870.08 U1.P11@2263.78,1854.33 pad.23@2279.53,1838.58 U1.R12@2295.28,1822.83 pad.24@2311.02,1807.09 pad.25@2342.52,1775.59 U1.U14@2358.27,1759.84 pad.26@2374.02,1744.09 U1.V15@2389.76,1728.35 pad.27@2405.51,1712.6 pad.28@2437.01,1681.1 U1.Y17@2452.76,1665.35 pad.29@2468.5,1649.61 U1.AA18@2484.25,1633.86 pad.30@2500,1618.11 U1.AB19@2515.75,1602.36 pad.31@2531.5,1586.61 U1.AC20@2547.24,1570.87 pad.32@2562.99,1555.12 U1.AD21@2578.74,1539.37 ; U1.C5@2074.8,2200.79 pad.100@2090.55,2185.04 ; U1.AE6@2106.3,1507.87 U1.AF7@2137.8,1476.38 pad.67@2153.54,1460.63 ; U1.AC6@2106.3,1570.87 pad.67@2122.05,1555.12 pad.67@2153.54,1523.62 pad.67@2185.04,1492.13 ; U1.W6@2106.3,1696.85 pad.61@2153.54,1649.61 U1.AB9@2200.79,1602.36 pad.64@2248.03,1555.12 U1.AD11@2263.78,1539.37 pad.66@2311.02,1492.13 U1.AG14@2358.27,1444.88 pad.68@2374.02,1429.13 ; U1.U6@2106.3,1759.84 pad.52@2153.54,1712.6 pad.53@2185.04,1681.1 pad.55@2248.03,1618.11 U1.AB11@2263.78,1602.36 pad.56@2279.53,1586.61 pad.58@2342.52,1523.62 U1.AE14@2358.27,1507.87 pad.59@2374.02,1492.13 ; U1.P6@2106.3,1854.33 pad.51@2122.05,1838.58 ; U1.N6@2106.3,1885.83 pad.51@2122.05,1870.08 pad.52@2153.54,1838.58 pad.53@2185.04,1807.09 pad.54@2216.54,1775.59 pad.55@2248.03,1744.09 U1.V11@2263.78,1728.35 pad.56@2279.53,1712.6 U1.W12@2295.28,1696.85 pad.57@2311.02,1681.1 pad.58@2342.52,1649.61 U1.AA14@2358.27,1633.86 pad.59@2374.02,1618.11 U1.AB15@2389.76,1602.36 pad.60@2405.51,1586.61 U1.AC16@2421.26,1570.87 pad.61@2437.01,1555.12 pad.62@2468.5,1523.62 pad.63@2500,1492.13 pad.64@2531.5,1460.63 U1.AG20@2547.24,1444.88 pad.65@2562.99,1429.13 ; U1.L6@2106.3,1948.82 pad.35@2153.54,1901.57 U1.P9@2200.79,1854.33 pad.38@2248.03,1807.09 pad.39@2279.53,1775.59 pad.41@2342.52,1712.6 U1.W14@2358.27,1696.85 pad.43@2405.51,1649.61 U1.AA16@2421.26,1633.86 U1.AB17@2452.76,1602.36 pad.46@2500,1555.12 U1.AD19@2515.75,1539.37 pad.47@2531.5,1523.62 ; U1.G6@2106.3,2074.8 U1.H7@2137.8,2043.31 U1.J8@2169.29,2011.81 pad.0@2185.04,1996.06 ; U1.D7@2137.8,2169.29 pad.100@2153.54,2153.54 ; U1.AJ8@2169.29,1381.89 pad.67@2185.04,1366.14 ; U1.G8@2169.29,2074.8 pad.0@2185.04,2059.05 U1.H9@2200.79,2043.31 U1.K11@2263.78,1980.31 U1.L12@2295.28,1948.82 U1.M13@2326.77,1917.32 pad.0@2342.52,1901.57 pad.1@2374.02,1870.08 U1.P15@2389.76,1854.33 pad.2@2405.51,1838.58 U1.R16@2421.26,1822.83 pad.3@2437.01,1807.09 U1.T17@2452.76,1791.34 pad.4@2468.5,1775.59 U1.U18@2484.25,1759.84 pad.5@2500,1744.09 U1.V19@2515.75,1728.35 pad.6@2531.5,1712.6 pad.7@2562.99,1681.1 U1.Y21@2578.74,1665.35 pad.8@2594.49,1649.61 U1.AA22@2610.24,1633.86 pad.9@2625.98,1618.11 pad.10@2657.48,1586.61 pad.11@2688.98,1555.12 U1.AD25@2704.72,1539.37 pad.12@2720.47,1523.62 ; U1.C9@2200.79,2200.79 pad.100@2216.54,2185.04 ; U1.AH10@2232.28,1413.39 pad.67@2248.03,1397.64 U1.AJ11@2263.78,1381.89 pad.67@2279.53,1366.14 pad.67@2311.02,1334.65 ; U1.L10@2232.28,1948.82 pad.0@2248.03,1933.07 U1.M11@2263.78,1917.32 pad.1@2279.53,1901.57 U1.N12@2295.28,1885.83 pad.2@2311.02,1870.08 pad.3@2342.52,1838.58 U1.R14@2358.27,1822.83 pad.4@2374.02,1807.09 pad.5@2405.51,1775.59 U1.U16@2421.26,1759.84 pad.6@2437.01,1744.09 U1.V17@2452.76,1728.35 pad.7@2468.5,1712.6 U1.W18@2484.25,1696.85 pad.8@2500,1681.1 pad.9@2531.5,1649.61 U1.AA20@2547.24,1633.86 pad.10@2562.99,1618.11 U1.AB21@2578.74,1602.36 pad.11@2594.49,1586.61 pad.12@2625.98,1555.12 pad.13@2657.48,1523.62 U1.AE24@2673.23,1507.87 pad.14@2688.98,1492.13 U1.AF25@2704.72,1476.38 pad.15@2720.47,1460.63 U1.AG26@2736.22,1444.88 pad.16@2751.97,1429.13 ; U1.G10@2232.28,2074.8 pad.0@2248.03,2059.06 U1.J12@2295.28,2011.81 U1.K13@2326.77,1980.31 U1.L14@2358.27,1948.82 U1.M15@2389.76,1917.32 U1.P17@2452.76,1854.33 U1.R18@2484.25,1822.83 U1.T19@2515.75,1791.34 U1.U20@2547.24,1759.84 U1.V21@2578.74,1728.35 U1.W22@2610.24,1696.85 pad.10@2625.98,1681.1 U1.AA24@2673.23,1633.86 U1.AB25@2704.72,1602.36 pad.13@2720.47,1586.61 ; U1.AG11@2263.78,1444.88 pad.67@2279.53,1429.13 ; U1.D11@2263.78,2169.29 pad.100@2279.53,2153.54 ; pad.0@2279.53,2090.55 U1.G12@2295.28,2074.8 U1.H13@2326.77,2043.31 pad.0@2342.52,2027.56 ; U1.AH13@2326.77,1413.39 pad.67@2342.52,1397.64 U1.AJ14@2358.27,1381.89 pad.67@2405.51,1334.65 ; U1.C13@2326.77,2200.79 pad.100@2342.52,2185.04 ; U1.G14@2358.27,2074.8 U1.H15@2389.76,2043.31 U1.J16@2421.26,2011.81 pad.80@2437.01,1996.06 pad.81@2468.5,1964.57 U1.L18@2484.25,1948.82 pad.82@2500,1933.07 U1.M19@2515.75,1917.32 pad.83@2531.5,1901.58 pad.84@2562.99,1870.08 U1.P21@2578.74,1854.33 pad.85@2594.49,1838.58 U1.R22@2610.24,1822.83 pad.86@2625.98,1807.09 U1.T23@2641.73,1791.34 pad.86@2657.48,1775.59 pad.86@2688.98,1744.09 U1.V25@2704.72,1728.35 pad.86@2720.47,1712.6 ; U1.K15@2389.76,1980.31 pad.0@2437.01,1933.07 pad.0@2468.5,1901.57 U1.P19@2515.75,1854.33 pad.0@2531.5,1838.58 U1.T21@2578.74,1791.34 pad.0@2594.49,1775.59 U1.U22@2610.24,1759.84 pad.0@2625.98,1744.09 U1.V23@2641.73,1728.35 pad.0@2657.48,1712.6 U1.Y25@2704.72,1665.35 pad.0@2720.47,1649.61 ; U1.AH16@2421.26,1413.39 pad.67@2468.5,1366.14 U1.AK18@2484.25,1350.39 pad.67@2500,1334.65 ; U1.AF16@2421.26,1476.38 U1.AG17@2452.76,1444.88 pad.68@2468.5,1429.13 ; U1.G16@2421.26,2074.8 pad.87@2437.01,2059.06 pad.88@2468.5,2027.56 U1.J18@2484.25,2011.81 pad.89@2500,1996.06 U1.K19@2515.75,1980.31 pad.90@2531.5,1964.57 U1.L20@2547.24,1948.82 pad.91@2562.99,1933.07 U1.M21@2578.74,1917.32 pad.92@2594.49,1901.58 U1.N22@2610.24,1885.83 pad.93@2625.98,1870.08 U1.P23@2641.73,1854.33 pad.94@2657.48,1838.58 pad.95@2688.98,1807.09 U1.T25@2704.72,1791.34 pad.95@2720.47,1775.59 ; U1.D16@2421.26,2169.29 pad.100@2437.01,2153.54 ; U1.G18@2484.25,2074.8 pad.96@2500,2059.06 U1.K21@2578.74,1980.31 U1.L22@2610.24,1948.82 pad.100@2625.98,1933.07 ; U1.C18@2484.25,2200.79 pad.100@2500,2185.04 ; U1.G20@2547.24,2074.8 U1.H21@2578.74,2043.31 pad.100@2594.49,2027.56 U1.J22@2610.24,2011.81 pad.100@2625.98,1996.06 U1.K23@2641.73,1980.31 pad.100@2657.48,1964.57 U1.L24@2673.23,1948.82 U1.M25@2704.72,1917.32 ; U1.D20@2547.24,2169.29 pad.100@2562.99,2153.54 ; U1.AF21@2578.74,1476.38 pad.49@2594.49,1460.63 ; U1.G22@2610.24,2074.8 pad.100@2625.98,2059.06 U1.H23@2641.73,2043.31 pad.100@2688.98,1996.06 U1.K25@2704.72,1980.31 pad.100@2720.47,1964.57 ; U1.C22@2610.24,2200.79 pad.100@2625.98,2185.04 ; U1.N24@2673.23,1885.83 pad.102@2688.98,1870.08 U1.P25@2704.72,1854.33 pad.103@2720.47,1838.58 ; U1.G24@2673.23,2074.8 pad.100@2688.98,2059.06 ; U1.D24@2673.23,2169.29 pad.100@2688.98,2153.54 ; U1.C26@2736.22,2200.79 pad.100@2751.97,2185.04 ; U1.J28@2799.21,2011.81 pad.100@2814.96,1996.06 ; U1.D28@2799.21,2169.29 pad.100@2814.96,2153.54 ; U1.AD29@2830.71,1539.37 pad.100@2846.46,1523.62 ; U1.AA29@2830.71,1633.86 pad.100@2846.46,1618.11 ; U1.U29@2830.71,1759.84 pad.100@2846.46,1744.09 ; U1.N29@2830.71,1885.83 pad.100@2846.46,1870.08 ; U1.AK30@2862.2,1350.39 pad.100@2877.95,1334.65 ; U1.A30@2862.2,2263.78 pad.100@2877.95,2248.03
  Bottom Layer w10: pad.100@1933.07,2216.54 pad.100@1964.57,2248.03 ; pad.70@2090.55,1649.61 pad.52@2153.54,1712.6 pad.2@2311.02,1870.08 pad.2@2374.02,1933.07 pad.80@2437.01,1996.06 pad.96@2500,2059.06 ; pad.51@2090.55,1838.58 pad.20@2185.04,1933.07 ; pad.17@2090.55,2027.56 pad.0@2122.05,2059.06 ; pad.67@2122.05,1555.12 pad.72@2153.54,1586.61 pad.54@2216.54,1649.61 pad.4@2374.02,1807.09 pad.4@2437.01,1870.08 pad.82@2500,1933.07 pad.100@2625.98,2059.06 ; pad.71@2122.05,1618.11 pad.0@2437.01,1933.07 pad.100@2562.99,2059.06 ; pad.51@2122.05,1744.09 pad.37@2216.54,1838.58 pad.1@2279.53,1901.57 pad.1@2342.52,1964.57 ; pad.52@2122.05,1807.09 pad.0@2248.03,1933.07 pad.0@2279.53,1964.57 pad.0@2311.02,1996.06 pad.78@2374.02,2059.06 ; pad.34@2122.05,1933.07 pad.0@2216.54,2027.56 pad.0@2248.03,2059.06 pad.0@2279.53,2090.55 ; pad.18@2122.05,1996.06 pad.0@2185.04,2059.05 ; pad.73@2185.04,1555.12 pad.0@2500,1870.08 pad.100@2657.48,2027.56 pad.100@2688.98,2059.06 pad.100@2720.47,2090.55 ; pad.74@2216.54,1523.62 pad.56@2279.53,1586.61 pad.6@2437.01,1744.09 pad.6@2500,1807.09 pad.84@2562.99,1870.08 pad.100@2688.98,1996.06 ; pad.75@2248.03,1492.13 pad.57@2311.02,1555.12 pad.7@2468.5,1712.6 pad.7@2531.5,1775.59 pad.85@2594.49,1838.58 pad.100@2720.47,1964.57 ; pad.0@2248.03,1996.06 pad.0@2311.02,2059.06 ; pad.66@2311.02,1492.13 pad.6@2531.5,1712.6 pad.102@2688.98,1870.08 ; pad.67@2342.52,1460.63 pad.95@2688.98,1807.09 pad.103@2720.47,1838.58 ; pad.79@2405.51,2027.56 pad.87@2437.01,2059.06 ; pad.62@2437.01,1492.13 pad.95@2720.47,1775.59 ; pad.63@2500,1492.13 pad.86@2720.47,1712.6 ; pad.65@2562.99,1429.13 pad.49@2594.49,1460.63 ; pad.33@2594.49,1523.62 pad.0@2720.47,1649.61 ; pad.13@2657.48,1523.62 pad.13@2720.47,1586.61 ; pad.14@2688.98,1492.13 pad.12@2720.47,1523.62 ; pad.100@2846.46,2216.54 pad.100@2877.95,2248.03 ; pad.100@2877.95,1334.65 C141.2@2909.45,1366.14
K2L_ALTCORECLKN: R11.1 U1.AH30
K2L_ALTCORECLKP: R11.2 U1.AG30
K2L_AVDDA1_1V8_FILT: C279.1 C281.1 L7.1 pad.100@2657.48,1996.06 pad.100@2660,2350 pad.100@2676.06,2392.76 pad.100@2694.65,2354.49 U1.J23 | length 22.3
  Top Layer w10: U1.J23@2641.73,2011.81 pad.100@2657.48,1996.06
K2L_AVDDA2_1V8_FILT: C295.1 C297.1 L9.1 pad.95@2720.47,1744.09 pad.100@2950,1720 pad.100@2950,1756.38 pad.100@3006.38,1736.38 U1.U25 | length 22.3
  Top Layer w10: U1.U25@2704.72,1759.84 pad.95@2720.47,1744.09
K2L_AVDDA3_1V8_FILT: C299.1 C301.1 L10.1 pad.67@2153.62,1250 pad.67@2170,1193.62 pad.67@2170,1260 pad.67@2311.02,1460.63 U1.AF12 | length 22.3
  Top Layer w10: U1.AF12@2295.28,1476.38 pad.67@2311.02,1460.63
K2L_AVDDA4_1V8_FILT: C303.1 C305.1 L11.1 pad.100@2751.97,1492.13 pad.100@2950,1490 pad.100@2950,1526.38 pad.100@3006.38,1510 U1.AE26 | length 22.3
  Top Layer w10: U1.AE26@2736.22,1507.87 pad.100@2751.97,1492.13
K2L_AVDDA5_1V8_FILT: C307.1 C309.1 L12.1 pad.100@2751.97,1460.63 pad.100@2950,1395.62 pad.100@2950,1430 pad.100@3006.38,1412 U1.AF26 | length 22.3
  Top Layer w10: U1.AF26@2736.22,1476.38 pad.100@2751.97,1460.63
K2L_AVDDA10_6_1V8_FILT: C268.1 C269.1 C270.1 C271.1 C272.1 C274.1 C277.1 L6.1 pad.98@2185.04,1964.57 pad.98@2279.53,1996.06 pad.98@2374.02,1996.06 pad.98@2380,2350 pad.98@2380,2380 pad.98@2410,2350 pad.98@2440,2380 pad.98@2446.38,2350 pad.98@2468.5,1996.06 pad.98@2594.49,1996.06 U1.J11 U1.J14 U1.J17 U1.J21 U1.K8 | length 111.4
  Top Layer w10: U1.K8@2169.29,1980.31 pad.98@2185.04,1964.57 ; U1.J11@2263.78,2011.81 pad.98@2279.53,1996.06 ; U1.J14@2358.27,2011.81 pad.98@2374.02,1996.06 ; U1.J17@2452.76,2011.81 pad.98@2468.5,1996.06 ; U1.J21@2578.74,2011.81 pad.98@2594.49,1996.06
K2L_BOOTCOMPLETE: R5.2 U1.AG3
K2L_CORECLKSEL0: U1.AE27
K2L_CORECLKSEL1: U1.AF27
K2L_CORESEL0_BOOTMODE13: U1.AE5
K2L_CORESEL1_BOOTMODE14: U1.AG6
K2L_CORESEL2_BOOTMODE15: U1.AH6
K2L_CS0_RXN0: U1.AJ19
K2L_CS0_RXN1: U1.AK20
K2L_CS0_RXP0: U1.AJ18
K2L_CS0_RXP1: U1.AK19
K2L_CS0_TXN0: U1.AH17
K2L_CS0_TXN1: U1.AG18
K2L_CS0_TXP0: U1.AH18
K2L_CS0_TXP1: U1.AG19
K2L_CS1_RXN0: U1.AJ16
K2L_CS1_RXN1: U1.AK17
K2L_CS1_RXP0: U1.AJ15
K2L_CS1_RXP1: U1.AK16
K2L_CS1_TXN0: U1.AH14
K2L_CS1_TXN1: U1.AG15
K2L_CS1_TXP0: U1.AH15
K2L_CS1_TXP1: U1.AG16
K2L_CS2_RXN0: U1.AJ25
K2L_CS2_RXN1: U1.AK26
K2L_CS2_RXP0: U1.AJ24
K2L_CS2_RXP1: U1.AK25
K2L_CS2_TXN0: U1.AH23
K2L_CS2_TXN1: U1.AG24
K2L_CS2_TXP0: U1.AH24
K2L_CS2_TXP1: U1.AG25
K2L_CS3_RXN0: U1.AK22
K2L_CS3_RXN1: U1.AK23
K2L_CS3_RXP0: U1.AJ21
K2L_CS3_RXP1: U1.AJ22
K2L_CS3_TXN0: U1.AH20
K2L_CS3_TXN1: U1.AG22
K2L_CS3_TXP0: U1.AH21
K2L_CS3_TXP1: U1.AG21
K2L_CSISC0CLKN: U1.AF18
K2L_CSISC0CLKP: U1.AF17
K2L_CSISC1CLKN: U1.AF15
K2L_CSISC1CLKP: U1.AF14
K2L_CSISC2CLKN: U1.AF24
K2L_CSISC2CLKP: U1.AF23
K2L_CSISC3CLKN: U1.AE19
K2L_CSISC3CLKP: U1.AE20
K2L_CVDD: C1.1 C2.1 C3.1 C4.1 C5.1 C6.1 C7.1 C8.1 C9.1 C10.1 C11.1 C12.1 C13.1 C14.1 C15.1 C16.1 C17.1 C18.1 C19.1 C20.1 C21.1 C22.1 C23.1 C24.1 C25.1 C26.1 C27.1 C28.1 C29.1 C30.1 C31.1 C32.1 C33.1 C34.1 C35.1 C36.1 C37.1 C38.1 C39.1 C40.1 C41.1 C42.1 C43.1 C44.1 C45.1 C46.1 C47.1 C48.1 C49.1 C50.1 C51.1 C52.1 C53.1 C54.1 C55.1 C56.1 C57.1 C58.1 C59.1 C60.1 C61.1 C62.1 C63.1 C64.1 C65.1 C66.1 C67.1 C68.1 C69.1 C70.1 C71.1 C72.1 C73.1 C74.1 C75.1 C76.1 C77.1 C78.1 C79.1 C80.1 C81.1 C82.1 C83.1 C84.1 C85.1 C86.1 C87.1 C88.1 C89.1 C90.1 C91.1 C92.1 C93.1 C94.1 C95.1 C96.1 C97.1 C98.1 C99.1 C100.1 pad.0@2311.02,1964.57 pad.0@2342.52,1870.08 pad.0@2374.02,1838.58 pad.0@2437.01,1964.57 pad.0@2500,1964.57 pad.1@2342.52,1933.07 pad.1@2405.51,1807.09 pad.1@2468.5,1933.07 pad.1@2531.5,1933.07 pad.2@2216.54,1933.07 pad.2@2279.53,1933.07 pad.2@2374.02,1901.57 pad.2@2374.02,1964.57 pad.2@2405.51,1933.07 pad.2@2437.01,1775.59 pad.2@2500,1901.57 pad.2@2562.99,1901.57 pad.3@2468.5,1744.09 pad.3@2562.99,1964.57 pad.4@2500,1712.6 pad.4@2594.49,1933.07 pad.5@2405.51,1618.11 pad.5@2468.5,1618.11 pad.5@2531.5,1681.1 pad.5@2594.49,1807.09 pad.5@2625.98,1775.59 pad.5@2625.98,1838.58 pad.5@2625.98,1901.57 pad.5@2625.98,1964.57 pad.6@2216.54,1870.08 pad.6@2562.99,1649.61 pad.7@2248.03,1838.58 pad.7@2594.49,1618.11 pad.8@2279.53,1807.09 pad.8@2311.02,1838.58 pad.9@2311.02,1775.59 pad.9@2342.52,1807.09 pad.10@2342.52,1744.09 pad.10@2374.02,1775.59 pad.11@2374.02,1712.6 pad.11@2405.51,1744.09 pad.12@2279.53,1744.09 pad.12@2437.01,1712.6 pad.13@2311.02,1712.6 pad.13@2468.63,1681.23 pad.14@2342.52,1681.1 pad.14@2500,1649.61 pad.14@2531.5,1618.11 pad.14@2562.99,1586.61 pad.14@2625.98,1586.61 pad.15@2279.53,1681.1 pad.16@2311.02,1649.61 pad.17@2342.52,1618.11 pad.18@2216.54,1681.1 pad.19@2248.03,1649.61 pad.20@2279.53,1618.11 pad.21@2216.54,1618.11 pad.22@2248.03,1586.61 pad.24@2468.5,1870.08 pad.25@2500,1838.58 pad.26@2531.5,1807.09 pad.27@2562.99,1775.59 pad.28@2594.49,1744.09 pad.29@2625.98,1712.6 pad.30@2468.5,1807.09 pad.31@2500,1775.59 pad.32@2531.5,1744.09 pad.33@2562.99,1712.6 pad.34@2594.49,1681.1 pad.35@2625.98,1649.61 U1.AA9 U1.AA11 U1.AA13 U1.AA15 U1.AA17 U1.AA19 U1.AA21 U1.AB10 U1.AB12 U1.AB20 U1.AB22 U1.K12 U1.K14 U1.K16 U1.K18 U1.K20 U1.K22 U1.L9 U1.L11 U1.L13 U1.L15 U1.L17 U1.L19 U1.L21 U1.M14 U1.M18 U1.M20 U1.M22 U1.N9 U1.N13 U1.N17 U1.P10 U1.P12 U1.P14 U1.P18 U1.P22 U1.R11 U1.R13 U1.R15 U1.R17 U1.R19 U1.R21 U1.T12 U1.T14 U1.T16 U1.T18 U1.T20 U1.T22 U1.U11 U1.U13 U1.U15 U1.U17 U1.U19 U1.U21 U1.V12 U1.V14 U1.V16 U1.V18 U1.V20 U1.V22 U1.W9 U1.W11 U1.W13 U1.W17 U1.W19 U1.W21 U1.Y10 U1.Y12 U1.Y18 U1.Y20 U1.Y22 | length 4637.3
  Top Layer w10: U1.AA9@2200.79,1633.86 U1.AB10@2232.28,1602.36 pad.22@2248.03,1586.61 pad.22@2251.2,1583.45 ; U1.W9@2200.79,1696.85 U1.AA11@2263.78,1633.86 U1.AB12@2295.28,1602.36 ; U1.N9@2200.79,1885.83 pad.6@2216.54,1870.08 pad.7@2248.03,1838.58 U1.R11@2263.78,1822.83 pad.8@2279.53,1807.09 pad.9@2311.02,1775.59 pad.10@2342.52,1744.09 U1.V14@2358.27,1728.35 ; U1.L9@2201.07,1948.54 U1.L9@2200.79,1948.82 pad.2@2216.54,1933.07 ; U1.W11@2263.78,1696.85 U1.Y12@2295.28,1665.35 U1.AA13@2326.77,1633.86 ; U1.U11@2263.78,1759.84 U1.V12@2295.28,1728.35 U1.W13@2326.77,1696.85 pad.14@2342.52,1681.1 ; U1.L11@2263.78,1948.82 pad.2@2279.53,1933.07 ; U1.P12@2295.28,1854.33 U1.R13@2326.77,1822.83 U1.U15@2389.76,1759.84 U1.V16@2421.26,1728.35 U1.W17@2452.76,1696.85 pad.14@2500,1649.61 U1.AA19@2515.75,1633.86 U1.AB20@2547.24,1602.36 pad.14@2562.99,1586.61 ; U1.K12@2295.28,1980.31 pad.0@2311.02,1964.57 pad.1@2342.52,1933.07 U1.M14@2358.27,1917.32 pad.2@2374.02,1901.57 ; U1.N13@2326.77,1885.83 pad.0@2342.52,1870.08 U1.P14@2358.27,1854.33 U1.R15@2389.76,1822.83 U1.T16@2421.26,1791.34 U1.U17@2452.76,1759.84 U1.V18@2484.25,1728.35 pad.4@2500,1712.6 U1.W19@2515.75,1696.85 pad.5@2531.5,1681.1 U1.Y20@2547.24,1665.35 U1.AA21@2578.74,1633.86 U1.AB22@2610.24,1602.36 pad.14@2625.98,1586.61 ; U1.K14@2358.27,1980.31 pad.2@2374.02,1964.57 U1.L15@2389.76,1948.82 pad.2@2405.51,1933.07 ; U1.AA15@2389.76,1633.86 pad.5@2405.51,1618.11 ; U1.K16@2421.26,1980.31 U1.M18@2484.25,1917.32 pad.2@2500,1901.57 ; U1.AA17@2452.76,1633.86 pad.5@2468.5,1618.11 ; U1.R17@2452.76,1822.83 pad.30@2468.5,1807.09 U1.T18@2484.25,1791.34 pad.31@2500,1775.59 U1.U19@2515.75,1759.84 pad.32@2531.5,1744.09 pad.33@2562.99,1712.6 pad.34@2594.49,1681.1 U1.Y22@2610.24,1665.35 ; U1.N17@2452.76,1885.83 pad.24@2468.5,1870.08 U1.P18@2484.25,1854.33 pad.25@2500,1838.58 U1.R19@2515.75,1822.83 pad.26@2531.5,1807.09 U1.T20@2547.24,1791.34 pad.27@2562.99,1775.59 U1.U21@2578.74,1759.84 pad.28@2594.49,1744.09 U1.V22@2610.24,1728.35 ; U1.K18@2484.25,1980.31 pad.0@2500,1964.57 pad.1@2531.5,1933.07 U1.M20@2547.24,1917.32 pad.2@2562.99,1901.57 ; U1.K20@2547.24,1980.31 pad.3@2562.99,1964.57 pad.4@2594.49,1933.07 U1.M22@2610.24,1917.32 pad.5@2625.98,1901.57 ; U1.R21@2578.74,1822.83 U1.T22@2610.24,1791.34 pad.5@2625.98,1775.59 ; U1.P22@2610.24,1854.33 pad.5@2625.98,1838.58 ; U1.K22@2610.24,1980.31 pad.5@2625.98,1964.57
  Bottom Layer w10: pad.21@2216.54,1618.11 pad.1@2405.51,1807.09 ; pad.22@2248.03,1586.61 pad.11@2405.51,1744.09 pad.2@2437.01,1775.59 pad.25@2500,1838.58 ; pad.12@2279.53,1744.09 pad.9@2311.02,1775.59 pad.9@2342.52,1807.09 pad.0@2374.02,1838.58 ; pad.8@2279.53,1807.09 pad.2@2374.02,1901.57 ; pad.2@2279.53,1933.07 pad.0@2311.02,1964.57 ; pad.1@2342.52,1933.07 pad.2@2374.02,1964.57 ; pad.12@2437.01,1712.6 pad.3@2468.5,1744.09 pad.26@2531.5,1807.09 ; pad.5@2468.5,1618.11 pad.5@2625.98,1775.59 ; pad.13@2468.5,1681.1 pad.13@2468.63,1681.23 pad.4@2500,1712.6 pad.5@2594.49,1807.09 pad.5@2625.98,1838.58 ; pad.24@2468.5,1870.08 pad.3@2562.99,1964.57 ; pad.1@2468.5,1933.07 pad.0@2500,1964.57 ; pad.14@2531.5,1618.11 pad.29@2625.98,1712.6 ; pad.14@2562.99,1586.61 pad.35@2625.98,1649.61 ; pad.2@2562.99,1901.57 pad.5@2625.98,1964.57
K2L_CVDD1V0: C109.1 C110.1 C111.1 C112.1 C113.1 C114.1 C115.1 C116.1 C117.1 C118.1 C119.1 C120.1 C121.1 C122.1 C123.1 C124.1 C126.1 C127.1 C128.1 C129.1 pad.15@2153.54,1933.07 pad.15@2185.04,1649.61 pad.15@2248.03,1901.57 pad.15@2279.53,1870.08 pad.15@2311.02,1901.57 pad.15@2374.02,1649.61 pad.15@2405.51,1681.1 pad.15@2405.51,1870.08 pad.15@2437.01,1649.61 pad.15@2437.01,1901.57 pad.15@2531.5,1870.08 pad.15@2562.99,1838.58 pad.15@2594.49,1555.12 pad.15@2594.49,1870.08 pad.15@2657.48,1933.07 pad.24@2437.01,1838.58 U1.AC21 U1.L7 U1.L23 U1.M10 U1.M12 U1.M16 U1.N11 U1.N15 U1.N19 U1.N21 U1.P16 U1.P20 U1.W15 U1.Y8 U1.Y14 U1.Y16 | length 623.6
  Top Layer w10: U1.L7@2137.8,1948.82 pad.15@2153.54,1933.07 ; U1.Y8@2169.29,1665.35 pad.15@2185.04,1649.61 ; U1.M10@2232.28,1917.32 pad.15@2248.03,1901.57 U1.N11@2263.78,1885.83 pad.15@2279.53,1870.08 ; U1.M12@2295.28,1917.32 pad.15@2311.02,1901.57 ; U1.Y14@2358.27,1665.35 pad.15@2374.02,1649.61 ; U1.W15@2389.76,1696.85 pad.15@2405.51,1681.1 U1.Y16@2421.26,1665.35 pad.15@2437.01,1649.61 ; U1.N15@2389.76,1885.83 pad.15@2405.51,1870.08 U1.P16@2421.26,1854.33 pad.24@2437.01,1838.58 ; U1.M16@2421.26,1917.32 pad.15@2437.01,1901.57 ; U1.N19@2515.75,1885.83 pad.15@2531.5,1870.08 U1.P20@2547.24,1854.33 pad.15@2562.99,1838.58 ; U1.AC21@2578.74,1570.87 pad.15@2594.49,1555.12 ; U1.N21@2578.74,1885.83 pad.15@2594.49,1870.08 ; U1.L23@2641.73,1948.82 pad.15@2657.48,1933.07
  Bottom Layer w10: pad.15@2279.53,1870.08 pad.15@2311.02,1901.57 ; pad.15@2374.02,1649.61 pad.15@2405.51,1681.1 ; pad.15@2405.51,1870.08 pad.15@2437.01,1901.57 ; pad.15@2562.99,1838.58 pad.15@2594.49,1870.08
K2L_DDR3ACLKN: R13.2 U1.G30
K2L_DDR3ACLKP: R13.1 U1.F30
K2L_DVDD0V85: C244.1 C245.1 C246.1 C247.1 C249.1 C251.1 C253.1 C255.1 C257.1 C259.1 L1.2 L2.2 L3.2 L4.2 pad.67@2512.99,1100 pad.67@2523.62,1061.5 pad.67@2530,1140 pad.67@2560,1060 pad.67@2560,1137.01 pad.67@2590,1140 pad.67@2600,1058.5 pad.67@2610,1100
